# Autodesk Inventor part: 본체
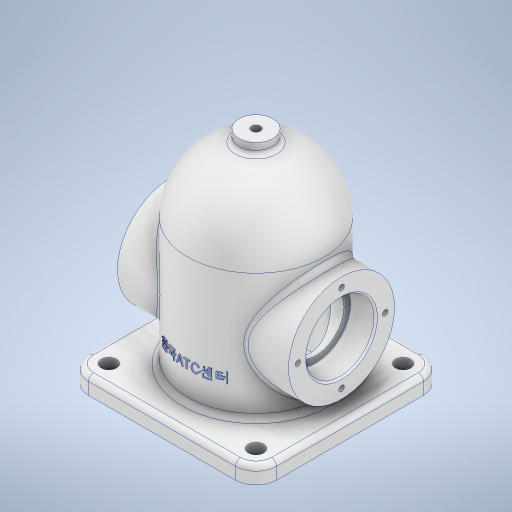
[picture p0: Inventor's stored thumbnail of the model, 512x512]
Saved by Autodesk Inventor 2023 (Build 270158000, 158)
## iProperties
Created: 2025-04
Part Number: 본체
Material: 알루미늄 6061
Document SubType Name: Modeling
Designer: user
Mass: 865.906 g
Surface Area: 800.755 cm^2
Volume: 320.706 cm^3
Density: 2.7 g/cm^3
Appearance: 알루미늄 - 평지
Author: user
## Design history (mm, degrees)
sketch "스케치1"
  geometry: L1 (-57.941, 0)-(9.657, 0) reference; L2 (0, -26.457)-(0, 158.741) reference; L3 (0, 0)-(-40, 0); L4 (-40, 0)-(-40, 84); L5 (-40, 84)-(0, 84); L6 (0, 84)-(0, 0); L7 (0, 124)-(0, 0); A1 r 40 centre (0, 84) between (0, 124) and (-40, 84); 2 further points
  constraints: 10 end point, 3 point on line, 2 parallel, 2 perpendicular, 2 point on circle, 1 centre point, 1 coincident, 1 horizontal, 1 midpoint
  dimensions: "d0" = 84 distance from line of point (-20, 0) L5; "d1" = 40 radius of A1
revolve "회전1" sketch "스케치1" stored, may be unused: angle "d2" = 90 deg
sketch "스케치2"
  geometry: L1 (-24.8, 0)-(148.8, 0) reference; L2 (0, -56)-(0, 56) reference; C1 r 31 at (48, 0); 1 further point
  constraints: 1 centre point, 1 horizontal alignment
  dimensions: "d3" = 62 diameter of C1; "d4" = 48 distance from line of L2 C1.centre
extrude "돌출1" join sketch "스케치2" stored distance "d5" = 100; taper "d6" = 0 deg
sketch "스케치3"
  geometry: L1 (-55, 55)-(55, 55); L2 (55, 55)-(55, -55); L3 (55, -55)-(-55, -55); L4 (-55, -55)-(-55, 55); L5 (-55, 55)-(55, -55); L6 (55, 55)-(-55, -55); 1 further point
  constraints: 12 end point, 2 midpoint, 2 parallel, 1 horizontal, 1 perpendicular
  dimensions: "d7" = 110 distance of L1.end L2.end; "d8" = 110 distance of L2.end L3.end
extrude "돌출2" join sketch "스케치3" distance "d9" = 10; taper "d10" = 0 deg
sketch "스케치5"
  geometry: L1 (40, 84)-(40, 79) reference; L2 (40, 79)-(50, 79) reference; L3 (50, 79)-(50, 17) reference; L4 (50, 17)-(40, 17) reference; L5 (40, 17)-(40, 10) reference; L6 (40, 10)-(55, 10) reference; L7 (55, 10)-(55, 0) reference; L8 (55, 0)-(-55, 0) reference; L9 (-55, 0)-(-55, 10) reference; L10 (-55, 10)-(-40, 10) reference; L11 (-40, 10)-(-40, 17) reference; L12 (-40, 17)-(-50, 17) reference; L13 (-50, 17)-(-50, 79) reference; L14 (-50, 79)-(-40, 79) reference; L15 (-40, 79)-(-40, 84) reference; L16 (32, 84)-(32, 0); L17 (55, 0)-(-55, 0) reference; L18 (0, 116)-(0, 0); L19 (32, 0)-(0, 0); L20 (0, -26.457)-(0, 158.741) reference; A1 r 40 centre (0, 84) between (40, 84) and (0, 124) reference; A2 r 40 centre (0, 84) between (0, 124) and (-40, 84) reference; A3 r 32 centre (0, 84) between (32, 84) and (0, 116); 1 further point
  constraints: 6 end point, 2 point on circle, 1 centre point, 1 collinear, 1 perpendicular, 1 point on line, 1 vertical
  dimensions: "d12" = 32 radius of A3; "d13" = 84 distance of L16.start L16.end
revolve "회전2" sketch "스케치5" stored, may be unused: angle "d14" = 90 deg
sketch "스케치6"
  geometry: C1 r 20 at (0, 0); C2 r 31 at (0, 0) reference; 1 further point
  constraints: 1 centre point, 1 concentric
  dimensions: "d15" = 40 diameter of C1
extrude "돌출3" cut sketch "스케치6" distance "d16" = 15; taper "d17" = 0 deg
sketch "스케치8"
  geometry: C1 r 16.5 at (0, 0); C2 r 20 at (0, 0) reference; 1 further point
  constraints: 1 centre point, 1 concentric
  dimensions: "d18" = 33 diameter of C1
extrude "돌출4" cut sketch "스케치8" extent not by distance; stored distance "d19" = 0; taper "d20" = 0 deg
node "작업 평면1"
sketch "스케치9"
  geometry: C1 r 32 at (55, 55) reference; C2 r 10 at (55, 55); 1 further point
  constraints: 1 centre point, 1 coincident
  dimensions: "d22" = 20 diameter of C2
extrude "돌출5" join sketch "스케치9" stored distance "d23" = 10; taper "d24" = 0 deg
sketch "스케치10" dims "d25" = 51
  geometry: L1 (0, -72.8)-(0, 100.8) reference; C1 r 20 at (0, 0) reference; 3 further points
  constraints: 2 vertical alignment, 3 other
hole "구멍1" sketch "스케치10" at (0, 25.5) diameter "d26" = 3.242; stored, may be unused: countersink angle "d30" = 90 deg, drill point angle "d32" = 118 deg; dims "d27" = 8, "d28" = 4, "d29" = 2, "d31" = 10
sketch "스케치11"
  geometry: 2 further points
  constraints: 1 coincident
hole "구멍2" sketch "스케치11" at (0, 0) diameter "d36" = 5.1881; stored, may be unused: countersink angle "d40" = 90 deg, drill point angle "d42" = 0 deg; dims "d37" = 12, "d38" = 4, "d39" = 2, "d41" = 16
fillet "모깎기1" dims "d43" = 0.3
fillet "모깎기2" dims "d44" = 12
sketch "스케치12"
  geometry: L1 (0, 77.497)-(0, -79.982) reference; L2 (-79.982, 0)-(77.497, 0) reference; C1 r 4.5 at (-43, -43); C2 r 4.5 at (-43, 43); C3 r 4.5 at (43, 43); C4 r 4.5 at (43, -43); A1 r 12 centre (-43, -43) between (-55, -43) and (-43, -55) reference; 1 further point
  constraints: 4 centre point, 3 symmetric about line, 1 coincident, 3 other
  dimensions: "d45" = 9 diameter of C1
extrude "돌출6" cut sketch "스케치12" extent not by distance; stored distance "d46" = 0; taper "d47" = 0 deg
fillet "모깎기3" dims "d48" = 3
fillet "모깎기4" dims "d49" = 3
fillet "모깎기5" dims "d50" = 3
chamfer "모따기1" distance "d51" = 1; stored, may be unused: second distance "d52" = 2, angle "d53" = 45 deg
node "작업 평면2"
sketch "스케치13"
  geometry: L1 (0, -24.8)-(0, 148.8) reference; L2 (-77, 0)-(77, 0) reference; 2 further points
  constraints: 1 vertical alignment, 1 other
  dimensions: "d58" = 30 distance from line of L2 point (0, 30)
feature "엠보싱1" sketch "스케치13" dims "d7" = 110, "d8" = 110, "d56" = 0.5, "d57" = 0
node "솔리드1"
mirror "미러1"
pattern_circular "원형 패턴1" dims angle "d34" = 360 deg
mirror "미러2"
node "절단 모서리 투영1"
feature "A9D066F2-1C7D-4E18-AEED-F7BC21143FA4" dims "d26" = 3.242, "d27" = 8, "d28" = 4, "d29" = 2, "d30" = 90 deg, "d31" = 10, "d32" = 118 deg
other parameters: "d21" = -129, "d54" = 99.75
